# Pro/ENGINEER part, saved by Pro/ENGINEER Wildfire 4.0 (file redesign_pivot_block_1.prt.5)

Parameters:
  METRIC = "NO"

Other parameters: PITCH, DRILL_POINT_ANGLE, DRILL_DEPTH, DRILL_DIAMETER, THREAD_DIAMETER, THREADS_PER_INCH, THREAD_DEPTH, THREAD_LENGTH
